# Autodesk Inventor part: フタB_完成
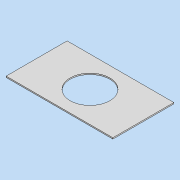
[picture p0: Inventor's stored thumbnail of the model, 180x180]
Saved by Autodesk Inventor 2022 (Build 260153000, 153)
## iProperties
Created: 2021-07
Part Number: フタB_完成
Material: 一般
Document SubType Name: Modeling
Designer: DesignLab
Density: 1 g/cm^3
Appearance: 既定
Author: DesignLab
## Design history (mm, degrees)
sketch "スケッチ1"
  geometry: L1 (0, 0)-(-350, 0); L2 (-350, 0)-(-350, -200); L3 (-350, -200)-(0, -200); L4 (0, -200)-(0, 0)
  constraints: 8 end point, 2 parallel, 1 horizontal, 1 perpendicular
  dimensions: "d0" = 350 distance of L3.end L2.end; "d1" = 200 distance of L2.end L1.end
extrude "押し出し1" new body sketch "スケッチ1" distance "d2" = 4; taper "d3" = 0 deg
sketch "スケッチ2"
  geometry: L1 (350, 200)-(0, 200) reference; L2 (0, 200)-(0, 0) reference; C1 r 65 at (175, 100); 2 further points
  constraints: 2 midpoint, 1 centre point
  dimensions: "d4" = 130 diameter of C1; "d9" = 175 distance from line of C1.centre L2 (= 0.5 x d0); "d10" = 100 distance from line of C1.centre L1 (= 0.5 x d1)
extrude "押し出し2" cut sketch "スケッチ2" extent not by distance; stored distance "d7" = 3; taper "d8" = 0 deg
node "ソリッド1"
